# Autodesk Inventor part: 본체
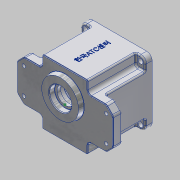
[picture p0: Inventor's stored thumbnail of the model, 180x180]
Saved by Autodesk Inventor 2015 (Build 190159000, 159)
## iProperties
Created: 2016-02
Part Number: 본체
Material: Aluminum 6061
Document SubType Name: Modeling
Designer: Administrator
Density: 2.7 g/cm^3
Appearance: Aluminum - Flat
Mass: 873.755 g
Surface Area: 761.301 cm^2
Volume: 323.613 cm^3
Author: Administrator
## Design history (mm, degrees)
sketch "Sketch1"
  geometry: L1 (33, -47)-(-33, -47); L2 (-33, -47)-(-33, 47); L3 (-33, 47)-(33, 47); L4 (33, 47)-(33, -47); L5 (33, -47)-(-33, 47); L6 (-33, -47)-(33, 47); L7 (70, -30)-(-70, -30); L8 (-70, -30)-(-70, 30); L9 (-70, 30)-(70, 30); L10 (70, 30)-(70, -30); L11 (70, -30)-(-70, 30); L12 (-70, -30)-(70, 30); 1 further point
  constraints: 24 end point, 4 midpoint, 4 parallel, 2 horizontal, 2 perpendicular
  dimensions: "d0" = 66 distance of L2.end L3.end; "d1" = 94 distance of L1.end L2.end; "d2" = 140 distance of L8.end L9.end; "d3" = 60 distance of L7.end L8.end
extrude "Extrusion1" new body sketch "Sketch1" distance "d4" = 13; taper "d5" = 0 deg
extrude "Extrusion2" cut sketch "Sketch1" distance "d6" = 70; taper "d7" = 0 deg
extrude "Extrusion3" join sketch "Sketch1" distance "d8" = 70; taper "d9" = 0 deg
sketch "Sketch2"
  geometry: L1 (47, 47)-(-47, 47); L2 (-47, 47)-(-47, -47); L3 (-47, -47)-(47, -47); L4 (47, -47)-(47, 47); L5 (47, 47)-(-47, -47); L6 (-47, 47)-(47, -47); 1 further point
  constraints: 12 end point, 2 midpoint, 2 parallel, 1 horizontal, 1 perpendicular
  dimensions: "d10" = 94 distance of L3.end L2.end; "d11" = 94 distance of L2.end L1.end
extrude "Extrusion4" join sketch "Sketch2" distance "d12" = 10; taper "d13" = 0 deg; dims "d14" = 57, "d15" = 0
sketch "Sketch3"
  geometry: L1 (-33, 30)-(-70, 30) reference; L2 (-70, 30)-(-70, -30) reference; L3 (-70, -30)-(-33, -30) reference; L4 (-33, -30)-(-33, -47) reference; L5 (-33, -47)-(33, -47) reference; L6 (33, -47)-(33, -30) reference; L7 (33, -30)-(70, -30) reference; L8 (70, -30)-(70, 30) reference; L9 (70, 30)-(33, 30) reference; L10 (33, 30)-(33, 47) reference; L11 (33, 47)-(-33, 47) reference; L12 (-33, 47)-(-33, 30) reference; L13 (-47, 30)-(-33, 30) reference; L14 (-33, 47)-(-33, 30) reference; L15 (-33, 47)-(-47, 47) reference; L16 (-47, 47)-(-47, 30) reference; L17 (33, 30)-(33, 47) reference; L18 (33, 30)-(47, 30) reference; L19 (47, 30)-(47, 47) reference; L20 (47, 47)-(33, 47) reference; L21 (47, -30)-(33, -30) reference; L22 (33, -47)-(33, -30) reference; L23 (33, -47)-(47, -47) reference; L24 (47, -47)-(47, -30) reference; L25 (-33, -30)-(-47, -30) reference; L26 (-47, -30)-(-47, -47) reference; L27 (-47, -47)-(-33, -47) reference; L28 (-33, -30)-(-33, -47) reference; L29 (-47, 47)-(-33, 47); L30 (-33, 47)-(-33, 30); L31 (-33, 30)-(-47, 30); L32 (-47, 30)-(-47, 47); L33 (33, 47)-(47, 47); L34 (47, 47)-(47, 30); L35 (47, 30)-(33, 30); L36 (33, 30)-(33, 47); L37 (33, -30)-(47, -30); L38 (47, -30)-(47, -47); L39 (47, -47)-(33, -47); L40 (33, -47)-(33, -30); L41 (-47, -30)-(-33, -30); L42 (-33, -30)-(-33, -47); L43 (-33, -47)-(-47, -47); L44 (-47, -47)-(-47, -30); 1 further point
  constraints: 32 end point, 8 parallel, 4 horizontal, 4 perpendicular
extrude "Extrusion5" cut sketch "Sketch3" distance "d16" = 57; taper "d17" = 0 deg
sketch "Sketch6"
  geometry: 2 further points
  constraints: 1 coincident
hole "Hole1" sketch "Sketch6" at (0, 0) diameter "d18" = 80; stored, may be unused: countersink angle "d22" = 90 deg, drill point angle "d24" = 0 deg; dims "d19" = 6, "d20" = 86, "d21" = 9, "d23" = 71
sketch "Sketch7"
  geometry: C1 r 43 at (0, 0) reference; A1 r 21 centre (0, -11) between (-8.978, 7.984) and (8.978, 7.984); A2 r 15 centre (0, 20) between (8.978, 7.984) and (-8.978, 7.984); 1 further point
  constraints: 4 point on circle, 2 centre point, 2 vertical alignment
  dimensions: "d25" = 21 radius of A1; "d26" = 11 distance of point (0, 0) A1.centre; "d27" = 15 radius of A2; "d28" = 20 distance of point (0, 0) A2.centre
extrude "Extrusion6" join sketch "Sketch7" distance "d29" = 7; taper "d30" = 0 deg
sketch "Sketch8"
  geometry: A1 r 15 centre (0, 20) between (8.978, 7.984) and (-8.978, 7.984) reference; A2 r 21 centre (0, -11) between (-8.978, 7.984) and (8.978, 7.984) reference; 2 further points
  constraints: 1 coincident
hole "Hole2" sketch "Sketch8" at (0, -11) diameter "d31" = 25; stored, may be unused: countersink angle "d35" = 90 deg, drill point angle "d37" = 0 deg; dims "d32" = 6, "d33" = 35, "d34" = 10, "d36" = 15
sketch "Sketch10"
  geometry: C1 r 17.5 at (0, -11) reference; A1 r 15 centre (0, 20) between (8.978, 7.984) and (-8.978, 7.984) reference; A2 r 21 centre (0, -11) between (-8.978, 7.984) and (8.978, 7.984) reference; 2 further points
  constraints: 1 coincident
hole "Hole3" sketch "Sketch10" at (0, 20) diameter "d41" = 19; stored, may be unused: countersink angle "d45" = 90 deg, drill point angle "d47" = 0 deg; dims "d42" = 6, "d43" = 22, "d44" = 7, "d46" = 8
sketch "Sketch11"
  geometry: C1 r 28 at (0, 11); A1 r 21 centre (0, 11) between (8.978, -7.984) and (-8.978, -7.984) reference; 1 further point
  constraints: 1 centre point, 1 coincident
  dimensions: "d48" = 56 diameter of C1
extrude "Extrusion8" join sketch "Sketch11" distance "d49" = 7; taper "d50" = -10 deg
sketch "Sketch12"
  geometry: C1 r 26.766 at (0, 0) reference; C2 r 16 at (0, 0); 1 further point
  constraints: 1 centre point, 1 coincident
  dimensions: "d51" = 32 diameter of C2
extrude "Extrusion9" cut sketch "Sketch12" distance "d52" = 8; taper "d53" = 0 deg
sketch "Sketch13"
  geometry: C1 r 43 at (0, 0) reference; A1 r 36 centre (0, 0) between (36, 0) and (-36, 0); A2 r 4 centre (36, 0) between (35.852, 3.997) and (35.852, -3.997); A3 r 4 centre (-36, 0) between (-35.852, -3.997) and (-35.852, 3.997); A4 r 40 centre (0, 0) between (39.148, -8.214) and (39.148, 8.214) reference; A5 r 3.5 centre (35.722, -7.495) between (39.148, -8.214) and (35.778, -3.995); A6 r 3.5 centre (35.722, 7.495) between (35.778, 3.995) and (39.148, 8.214); A7 r 3.5 centre (-35.722, -7.495) between (-35.778, -3.995) and (-39.148, -8.214); A8 r 3.5 centre (-35.722, 7.495) between (-39.148, 8.214) and (-35.778, 3.995); A9 r 40 centre (0, 0) between (39.148, -8.214) and (39.148, 8.214); A10 r 40 centre (0, 0) between (-39.148, 8.214) and (-39.148, -8.214); 1 further point
  constraints: 30 point on circle, 9 centre point, 8 tangent, 3 coincident, 2 horizontal alignment
  dimensions: "d54" = 36 radius of A1; "d55" = 4 radius of A2; "d56" = 4 radius of A3; "d57" = 3.5 radius of A5; "d58" = 3.5 radius of A6; "d59" = 3.5 radius of A7; "d60" = 3.5 radius of A8
extrude "Extrusion10" join sketch "Sketch13" stored distance "d61" = 8; taper "d62" = 0 deg
sketch "Sketch14" dims "d0" = 66, "d1" = 94
  geometry: L1 (66, 0)-(0, 0) reference; L2 (-14, 80)-(80, 80) reference; 3 further points
  constraints: 1 midpoint, 1 vertical alignment, 1 other
  dimensions: "d63" = 40 distance from line of L2 point (33, 40)
emboss "Emboss1" sketch "Sketch14" dims "d0" = 66, "d1" = 94, "d10" = 94, "d11" = 94, "d64" = 0.5, "d65" = 0
chamfer "Chamfer1" distance "d66" = 10; stored, may be unused: second distance "d67" = 2, angle "d68" = 45 deg
fillet "Fillet1" dims "d69" = 5
fillet "Fillet2" dims "d70" = 8
fillet "Fillet3" dims "d71" = 5
sketch "Sketch17"
  geometry: L1 (-68.536, 21.464)-(-61.464, 28.536) reference; L2 (-70, 17.929)-(-70, -17.929) reference; L3 (-61.464, -28.536)-(-68.536, -21.464) reference; L4 (-57.929, -30)-(-38, -30) reference; L5 (-33, -35)-(-33, -47) reference; L6 (-33, -47)-(33, -47) reference; L7 (33, -47)-(33, -35) reference; L8 (38, -30)-(57.929, -30) reference; L9 (68.536, -21.464)-(61.464, -28.536) reference; L10 (70, -17.929)-(70, 17.929) reference; L11 (61.464, 28.536)-(68.536, 21.464) reference; L12 (57.929, 30)-(38, 30) reference; L13 (33, 35)-(33, 47) reference; L14 (33, 47)-(-33, 47) reference; L15 (-33, 47)-(-33, 35) reference; L16 (-38, 30)-(-57.929, 30) reference; L17 (-60.757, 27.828)-(-67.828, 20.757); L18 (-69, 17.929)-(-69, -17.929); L19 (-67.828, -20.757)-(-60.757, -27.828); L20 (-57.929, -29)-(-38, -29); L21 (-32, -35)-(-32, -46); L22 (-32, -46)-(32, -46); L23 (32, -46)-(32, -35); L24 (38, -29)-(57.929, -29); L25 (60.757, -27.828)-(67.828, -20.757); L26 (69, -17.929)-(69, 17.929); L27 (67.828, 20.757)-(60.757, 27.828); L28 (57.929, 29)-(38, 29); L29 (32, 35)-(32, 46); L30 (32, 46)-(-32, 46); L31 (-32, 46)-(-32, 35); L32 (-38, 29)-(-57.929, 29); C1 r 28 at (0, 11) reference; A1 r 5 centre (-57.929, 25) between (-57.929, 30) and (-61.464, 28.536) reference; A2 r 5 centre (-65, 17.929) between (-68.536, 21.464) and (-70, 17.929) reference; A3 r 5 centre (-65, -17.929) between (-70, -17.929) and (-68.536, -21.464) reference; A4 r 5 centre (-57.929, -25) between (-61.464, -28.536) and (-57.929, -30) reference; A5 r 5 centre (-38, -35) between (-33, -35) and (-38, -30) reference; A6 r 5 centre (38, -35) between (38, -30) and (33, -35) reference; A7 r 5 centre (57.929, -25) between (57.929, -30) and (61.464, -28.536) reference; A8 r 5 centre (65, -17.929) between (68.536, -21.464) and (70, -17.929) reference; A9 r 5 centre (65, 17.929) between (70, 17.929) and (68.536, 21.464) reference; A10 r 5 centre (57.929, 25) between (61.464, 28.536) and (57.929, 30) reference; A11 r 5 centre (38, 35) between (33, 35) and (38, 30) reference; A12 r 5 centre (-38, 35) between (-38, 30) and (-33, 35) reference; A13 r 4 centre (-57.929, 25) between (-57.929, 29) and (-60.757, 27.828); A14 r 4 centre (-65, 17.929) between (-67.828, 20.757) and (-69, 17.929); A15 r 4 centre (-65, -17.929) between (-69, -17.929) and (-67.828, -20.757); A16 r 4 centre (-57.929, -25) between (-60.757, -27.828) and (-57.929, -29); A17 r 6 centre (-38, -35) between (-32, -35) and (-38, -29); A18 r 6 centre (38, -35) between (38, -29) and (32, -35); A19 r 4 centre (57.929, -25) between (57.929, -29) and (60.757, -27.828); A20 r 4 centre (65, -17.929) between (67.828, -20.757) and (69, -17.929); A21 r 4 centre (65, 17.929) between (69, 17.929) and (67.828, 20.757); A22 r 4 centre (57.929, 25) between (60.757, 27.828) and (57.929, 29); A23 r 6 centre (38, 35) between (32, 35) and (38, 29); A24 r 6 centre (-38, 35) between (-38, 29) and (-32, 35); 1 further point
  constraints: 32 end point, 24 point on circle, 12 centre point, 27 other
  dimensions: "d75" = 1 distance between parallel lines of L16 L32
extrude "Extrusion12" cut sketch "Sketch17" distance "d76" = 1; taper "d77" = 0 deg
sketch "Sketch19"
  geometry: L1 (60, 19)-(-60, 19); L2 (-60, 19)-(-60, -19); L3 (-60, -19)-(60, -19); L4 (60, -19)-(60, 19); L5 (60, 19)-(-60, -19); L6 (-60, 19)-(60, -19); 5 further points
  constraints: 12 end point, 4 coincident, 2 midpoint, 2 parallel, 1 horizontal, 1 perpendicular
  dimensions: "d80" = 120 distance of L3.end L2.end; "d81" = 38 distance of L2.end L1.end
hole "Hole4" sketch "Sketch19" at (60, -19), (60, 19), (-60, -19), (-60, 19) diameter "d82" = 5; stored, may be unused: countersink angle "d86" = 90 deg, drill point angle "d88" = 0 deg; dims "d83" = 6, "d84" = 9, "d85" = 4, "d87" = 13
sketch "Sketch20"
  geometry: L1 (-40, -40)-(40, -40); L2 (40, -40)-(40, 40); L3 (40, 40)-(-40, 40); L4 (-40, 40)-(-40, -40); L5 (-40, -40)-(40, 40); L6 (40, -40)-(-40, 40); 5 further points
  constraints: 12 end point, 4 coincident, 2 midpoint, 2 parallel, 1 horizontal, 1 perpendicular
  dimensions: "d89" = 80 distance of L3.end L2.end; "d90" = 80 distance of L2.end L1.end
hole "Hole5" sketch "Sketch20" at (-40, 40), (-40, -40), (40, -40), (40, 40) diameter "d91" = 7; stored, may be unused: countersink angle "d95" = 90 deg, drill point angle "d97" = 0 deg; dims "d92" = 6, "d93" = 9, "d94" = 4, "d96" = 10
sketch "Sketch21"
  geometry: A1 r 36 centre (0, 0) between (36, 0) and (-36, 0); 1 further point
  constraints: 2 horizontal alignment, 2 point on circle, 1 centre point, 1 coincident
  dimensions: "d98" = 36 radius of A1
hole "Hole6" sketch "Sketch21" at (36, 0), (-36, 0) diameter "d99" = 3.242; stored, may be unused: countersink angle "d103" = 90 deg, drill point angle "d105" = 118 deg; dims "d100" = 7, "d101" = 9, "d102" = 4, "d104" = 9
sketch "Sketch23"
  geometry: 1 further point
fillet "Fillet5" dims "d107" = 0.3
fillet "Fillet6" dims "d108" = 3
chamfer "Chamfer2" distance "d109" = 1; stored, may be unused: second distance "d110" = 2, angle "d111" = 45 deg
fillet "Fillet7" dims "d112" = 2
fillet "Fillet8" dims "d113" = 2
sketch "Sketch24"
  geometry: 1 further point
fillet "Fillet9" dims "d114" = 2
body "Solid1"
node "Projected Loop1"
node "Projected Loop2"
node "Projected Loop3"
node "Projected Loop4"
node "Projected Loop5"
node "Projected Loop6"
node "Projected Loop7"
node "Projected Loop8"
node "Projected Loop10"
